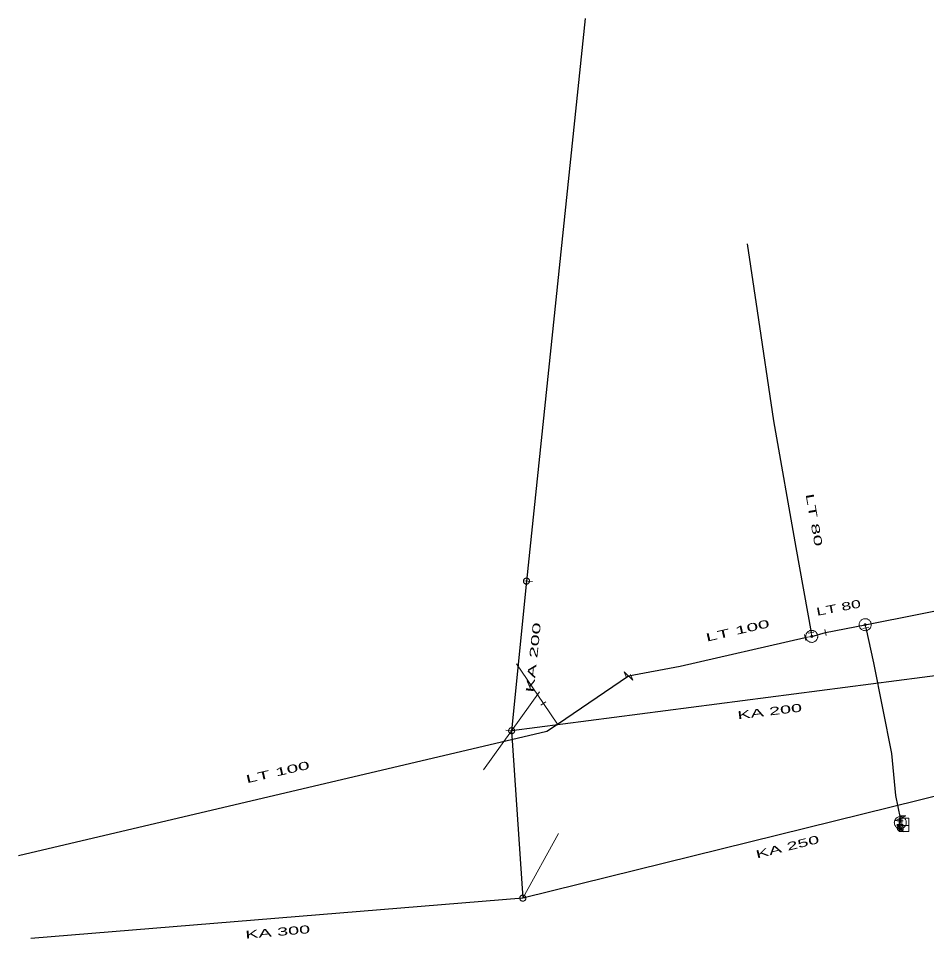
# Model space of a CAD drawing. Extents: x -791009 to -790862, y -978091 to -978015.
# Drawn here: x -791008.6 to -790933, y -978091.4 to -978014.8 of the extents above; entities that cross this region are included whole.
import ezdxf
from ezdxf.enums import TextEntityAlignment as Align

# ---------------------------------------------------------------- set-up
doc = ezdxf.new("R2010")
doc.units = 0
doc.header["$LTSCALE"] = 0.27
doc.layers.add('1', color=7, linetype='Continuous', lineweight=13)

msp = doc.modelspace()

# ---------------------------------------------------------------- linework, layer by layer
at = {"layer": '1', "lineweight": 25}
for p, q in [((-790961.436, -978014.787), (-790966.337, -978061.642)), ((-790966.337, -978061.642), (-790967.57, -978074.1)), ((-790924.866, -978068.572), (-790967.57, -978074.1)), ((-790967.57, -978074.1), (-790966.64, -978088.039)), ((-790923.129, -978077.28), (-790966.64, -978088.039)), ((-790935.21, -978081.39), (-790935.21, -978081.598)), ((-790935.21, -978081.598), (-790935.21, -978081.752)), ((-790966.64, -978088.039), (-791007.609, -978091.399))]:
    msp.add_line(p, q, dxfattribs=at)
at = {"layer": '1'}
for p, q in [((-790966.588, -978061.62), (-790965.846, -978061.684)), ((-790937.837, -978065.464), (-790938.32, -978065.575)), ((-790938.079, -978065.52), (-790938.133, -978065.27)), ((-790943.084, -978066.581), (-790943.195, -978066.098)), ((-790943.14, -978066.34), (-790942.581, -978066.243)), ((-790942.883, -978065.977), (-790942.396, -978065.882)), ((-790942.64, -978065.93), (-790942.581, -978066.243)), ((-790941.481, -978065.677), (-790941.378, -978066.162)), ((-790967.171, -978068.517), (-790964.93, -978071.829)), ((-790958.207, -978069.185), (-790958.004, -978069.654)), ((-790967.57, -978074.1), (-790965.239, -978070.85)), ((-790964.726, -978071.686), (-790965.133, -978071.971)), ((-790963.765, -978073.55), (-790964.93, -978071.829)), ((-790967.57, -978074.1), (-790969.901, -978077.35)), ((-790967.318, -978074.121), (-790968.06, -978074.057)), ((-790934.744, -978081.182), (-790935.255, -978081.194)), ((-790935.5, -978081.923), (-790934.919, -978082.505)), ((-790935.458, -978081.597), (-790934.962, -978081.598)), ((-790934.962, -978081.899), (-790935.458, -978081.898)), ((-790935.21, -978081.752), (-790935.21, -978081.899)), ((-790935.21, -978081.899), (-790935.21, -978082.214)), ((-790935.21, -978082.214), (-790935.21, -978082.489)), ((-790966.64, -978088.039), (-790963.67, -978082.66)), ((-790966.388, -978088.021), (-790967.13, -978088.073))]:
    msp.add_line(p, q, dxfattribs=at)
at = {"layer": '1', "lineweight": 25}
for points in [[(-790947.971, -978033.563), (-790947.133, -978039.149), (-790945.76, -978048.3), (-790943.91, -978058.85), (-790942.64, -978065.93)], [(-790938.133, -978065.27), (-790929.05, -978063.48), (-790923.92, -978062), (-790911.73, -978059.93), (-790910.719, -978060.899), (-790908.14, -978061.89), (-790895.21, -978059.059), (-790884.6, -978056.66), (-790868.534, -978052.874), (-790866.21, -978052.43), (-790863.219, -978051.91)], [(-790942.581, -978066.243), (-790941.43, -978065.92), (-790938.133, -978065.27)], [(-790938.079, -978065.52), (-790937.44, -978068.449), (-790935.949, -978075.989), (-790935.62, -978079.48), (-790935.21, -978081.39)], [(-790957.84, -978069.539), (-790953.55, -978068.73), (-790943.14, -978066.34)], [(-791008.64, -978084.48), (-790964.631, -978074.136), (-790963.765, -978073.55), (-790957.84, -978069.539)]]:
    msp.add_lwpolyline(points, dxfattribs=at)
at = {"layer": '1'}
for points in [[(-790966.315, -978061.39), (-790966.341, -978061.39), (-790966.367, -978061.392), (-790966.393, -978061.396), (-790966.418, -978061.403), (-790966.443, -978061.413), (-790966.466, -978061.425), (-790966.489, -978061.44), (-790966.508, -978061.457), (-790966.527, -978061.476), (-790966.543, -978061.497), (-790966.557, -978061.52), (-790966.569, -978061.543), (-790966.577, -978061.568), (-790966.583, -978061.594), (-790966.588, -978061.62), (-790966.588, -978061.646), (-790966.586, -978061.672), (-790966.582, -978061.698), (-790966.575, -978061.724), (-790966.565, -978061.748), (-790966.553, -978061.771), (-790966.538, -978061.794), (-790966.521, -978061.813), (-790966.502, -978061.832), (-790966.481, -978061.848), (-790966.458, -978061.862), (-790966.435, -978061.874), (-790966.41, -978061.883), (-790966.384, -978061.889), (-790966.358, -978061.893), (-790966.332, -978061.894), (-790966.306, -978061.892), (-790966.28, -978061.887), (-790966.254, -978061.88), (-790966.23, -978061.87), (-790966.207, -978061.858), (-790966.184, -978061.843), (-790966.165, -978061.826), (-790966.146, -978061.807), (-790966.13, -978061.786), (-790966.116, -978061.764), (-790966.104, -978061.74), (-790966.095, -978061.715), (-790966.089, -978061.689), (-790966.085, -978061.663), (-790966.084, -978061.637), (-790966.086, -978061.611), (-790966.091, -978061.585), (-790966.098, -978061.56), (-790966.108, -978061.535), (-790966.12, -978061.512), (-790966.135, -978061.489), (-790966.152, -978061.47), (-790966.171, -978061.451), (-790966.192, -978061.435), (-790966.214, -978061.421), (-790966.238, -978061.409), (-790966.263, -978061.401), (-790966.289, -978061.395)], [(-790937.633, -978065.27), (-790937.636, -978065.218), (-790937.644, -978065.166), (-790937.658, -978065.116), (-790937.676, -978065.067), (-790937.7, -978065.02), (-790937.729, -978064.976), (-790937.762, -978064.936), (-790937.799, -978064.899), (-790937.839, -978064.866), (-790937.883, -978064.837), (-790937.93, -978064.813), (-790937.979, -978064.795), (-790938.029, -978064.781), (-790938.081, -978064.773), (-790938.133, -978064.77), (-790938.185, -978064.773), (-790938.237, -978064.781), (-790938.288, -978064.795), (-790938.336, -978064.813), (-790938.383, -978064.837), (-790938.427, -978064.866), (-790938.468, -978064.899), (-790938.505, -978064.936), (-790938.538, -978064.976), (-790938.566, -978065.02), (-790938.59, -978065.067), (-790938.609, -978065.116), (-790938.622, -978065.166), (-790938.63, -978065.218), (-790938.633, -978065.27), (-790938.63, -978065.322), (-790938.622, -978065.374), (-790938.609, -978065.425), (-790938.59, -978065.473), (-790938.566, -978065.52), (-790938.538, -978065.564), (-790938.505, -978065.605), (-790938.468, -978065.642), (-790938.427, -978065.675), (-790938.383, -978065.703), (-790938.336, -978065.727), (-790938.288, -978065.746), (-790938.237, -978065.759), (-790938.185, -978065.767), (-790938.133, -978065.77), (-790938.081, -978065.767), (-790938.029, -978065.759), (-790937.979, -978065.746), (-790937.93, -978065.727), (-790937.883, -978065.703), (-790937.839, -978065.675), (-790937.799, -978065.642), (-790937.762, -978065.605), (-790937.729, -978065.564), (-790937.7, -978065.52), (-790937.676, -978065.473), (-790937.658, -978065.425), (-790937.644, -978065.374), (-790937.636, -978065.322)], [(-790938.051, -978065.27), (-790938.051, -978065.261), (-790938.053, -978065.253), (-790938.055, -978065.245), (-790938.058, -978065.237), (-790938.062, -978065.229), (-790938.067, -978065.222), (-790938.072, -978065.215), (-790938.078, -978065.209), (-790938.085, -978065.204), (-790938.092, -978065.199), (-790938.1, -978065.195), (-790938.108, -978065.192), (-790938.116, -978065.19), (-790938.124, -978065.188), (-790938.133, -978065.188), (-790938.142, -978065.188), (-790938.15, -978065.19), (-790938.158, -978065.192), (-790938.166, -978065.195), (-790938.174, -978065.199), (-790938.181, -978065.204), (-790938.188, -978065.209), (-790938.194, -978065.215), (-790938.2, -978065.222), (-790938.204, -978065.229), (-790938.208, -978065.237), (-790938.211, -978065.245), (-790938.213, -978065.253), (-790938.215, -978065.261), (-790938.215, -978065.27), (-790938.215, -978065.279), (-790938.213, -978065.287), (-790938.211, -978065.295), (-790938.208, -978065.303), (-790938.204, -978065.311), (-790938.2, -978065.318), (-790938.194, -978065.325), (-790938.188, -978065.331), (-790938.181, -978065.337), (-790938.174, -978065.341), (-790938.166, -978065.345), (-790938.158, -978065.348), (-790938.15, -978065.35), (-790938.142, -978065.352), (-790938.133, -978065.352), (-790938.124, -978065.352), (-790938.116, -978065.35), (-790938.108, -978065.348), (-790938.1, -978065.345), (-790938.092, -978065.341), (-790938.085, -978065.337), (-790938.078, -978065.331), (-790938.072, -978065.325), (-790938.067, -978065.318), (-790938.062, -978065.311), (-790938.058, -978065.303), (-790938.055, -978065.295), (-790938.053, -978065.287), (-790938.051, -978065.279)], [(-790942.58, -978065.743), (-790942.632, -978065.745), (-790942.684, -978065.753), (-790942.734, -978065.767), (-790942.783, -978065.785), (-790942.83, -978065.809), (-790942.874, -978065.838), (-790942.914, -978065.871), (-790942.951, -978065.908), (-790942.984, -978065.948), (-790943.013, -978065.992), (-790943.037, -978066.039), (-790943.055, -978066.088), (-790943.069, -978066.138), (-790943.077, -978066.19), (-790943.081, -978066.242), (-790943.078, -978066.294), (-790943.07, -978066.346), (-790943.056, -978066.397), (-790943.038, -978066.445), (-790943.014, -978066.492), (-790942.985, -978066.536), (-790942.952, -978066.577), (-790942.915, -978066.614), (-790942.875, -978066.647), (-790942.831, -978066.675), (-790942.784, -978066.699), (-790942.735, -978066.718), (-790942.685, -978066.731), (-790942.633, -978066.739), (-790942.581, -978066.743), (-790942.529, -978066.74), (-790942.477, -978066.732), (-790942.426, -978066.719), (-790942.378, -978066.7), (-790942.331, -978066.676), (-790942.287, -978066.648), (-790942.246, -978066.615), (-790942.209, -978066.578), (-790942.176, -978066.537), (-790942.148, -978066.493), (-790942.124, -978066.446), (-790942.105, -978066.398), (-790942.092, -978066.347), (-790942.084, -978066.295), (-790942.081, -978066.243), (-790942.083, -978066.191), (-790942.091, -978066.139), (-790942.104, -978066.089), (-790942.123, -978066.04), (-790942.147, -978065.993), (-790942.175, -978065.949), (-790942.208, -978065.909), (-790942.245, -978065.872), (-790942.286, -978065.839), (-790942.33, -978065.81), (-790942.377, -978065.786), (-790942.425, -978065.768), (-790942.476, -978065.754), (-790942.528, -978065.746)], [(-790942.58, -978066.161), (-790942.589, -978066.161), (-790942.597, -978066.162), (-790942.605, -978066.164), (-790942.613, -978066.167), (-790942.621, -978066.171), (-790942.628, -978066.176), (-790942.635, -978066.181), (-790942.641, -978066.187), (-790942.646, -978066.194), (-790942.651, -978066.201), (-790942.655, -978066.209), (-790942.658, -978066.217), (-790942.66, -978066.225), (-790942.663, -978066.233), (-790942.663, -978066.242), (-790942.663, -978066.251), (-790942.661, -978066.259), (-790942.659, -978066.267), (-790942.656, -978066.275), (-790942.652, -978066.283), (-790942.647, -978066.29), (-790942.642, -978066.297), (-790942.636, -978066.303), (-790942.629, -978066.309), (-790942.622, -978066.313), (-790942.614, -978066.317), (-790942.606, -978066.32), (-790942.598, -978066.322), (-790942.59, -978066.325), (-790942.581, -978066.325), (-790942.572, -978066.325), (-790942.564, -978066.323), (-790942.556, -978066.321), (-790942.548, -978066.318), (-790942.54, -978066.314), (-790942.533, -978066.31), (-790942.526, -978066.304), (-790942.52, -978066.298), (-790942.514, -978066.291), (-790942.51, -978066.284), (-790942.506, -978066.276), (-790942.503, -978066.268), (-790942.501, -978066.26), (-790942.499, -978066.252), (-790942.499, -978066.243), (-790942.499, -978066.234), (-790942.5, -978066.226), (-790942.502, -978066.218), (-790942.505, -978066.21), (-790942.509, -978066.202), (-790942.513, -978066.195), (-790942.519, -978066.188), (-790942.525, -978066.182), (-790942.532, -978066.177), (-790942.539, -978066.172), (-790942.547, -978066.168), (-790942.555, -978066.165), (-790942.563, -978066.163), (-790942.571, -978066.161)], [(-790967.591, -978074.351), (-790967.565, -978074.351), (-790967.539, -978074.349), (-790967.513, -978074.345), (-790967.488, -978074.338), (-790967.463, -978074.328), (-790967.44, -978074.316), (-790967.417, -978074.301), (-790967.398, -978074.284), (-790967.379, -978074.265), (-790967.363, -978074.244), (-790967.349, -978074.221), (-790967.337, -978074.198), (-790967.329, -978074.173), (-790967.323, -978074.147), (-790967.318, -978074.121), (-790967.318, -978074.095), (-790967.32, -978074.069), (-790967.324, -978074.043), (-790967.331, -978074.017), (-790967.341, -978073.993), (-790967.353, -978073.97), (-790967.368, -978073.947), (-790967.385, -978073.928), (-790967.404, -978073.909), (-790967.425, -978073.893), (-790967.448, -978073.879), (-790967.471, -978073.867), (-790967.496, -978073.858), (-790967.522, -978073.852), (-790967.548, -978073.848), (-790967.574, -978073.847), (-790967.6, -978073.849), (-790967.626, -978073.854), (-790967.652, -978073.861), (-790967.676, -978073.871), (-790967.699, -978073.883), (-790967.722, -978073.898), (-790967.741, -978073.915), (-790967.76, -978073.934), (-790967.776, -978073.955), (-790967.79, -978073.977), (-790967.802, -978074.001), (-790967.811, -978074.026), (-790967.817, -978074.052), (-790967.821, -978074.078), (-790967.822, -978074.104), (-790967.82, -978074.13), (-790967.815, -978074.156), (-790967.808, -978074.181), (-790967.798, -978074.206), (-790967.786, -978074.229), (-790967.771, -978074.252), (-790967.754, -978074.271), (-790967.735, -978074.29), (-790967.714, -978074.306), (-790967.692, -978074.32), (-790967.668, -978074.332), (-790967.643, -978074.34), (-790967.617, -978074.346)], [(-790934.71, -978081.752), (-790934.713, -978081.7), (-790934.721, -978081.647), (-790934.735, -978081.598), (-790934.752, -978081.549), (-790934.777, -978081.502), (-790934.806, -978081.458), (-790934.838, -978081.418), (-790934.875, -978081.38), (-790934.916, -978081.348), (-790934.96, -978081.319), (-790935.007, -978081.294), (-790935.056, -978081.277), (-790935.105, -978081.263), (-790935.157, -978081.255), (-790935.21, -978081.252), (-790935.262, -978081.255), (-790935.314, -978081.263), (-790935.365, -978081.277), (-790935.413, -978081.294), (-790935.46, -978081.319), (-790935.504, -978081.348), (-790935.544, -978081.38), (-790935.581, -978081.418), (-790935.615, -978081.458), (-790935.642, -978081.502), (-790935.667, -978081.549), (-790935.686, -978081.598), (-790935.698, -978081.647), (-790935.706, -978081.7), (-790935.71, -978081.752), (-790935.706, -978081.804), (-790935.698, -978081.856), (-790935.686, -978081.907), (-790935.667, -978081.955), (-790935.642, -978082.002), (-790935.615, -978082.046), (-790935.581, -978082.087), (-790935.544, -978082.124), (-790935.504, -978082.157), (-790935.46, -978082.184), (-790935.413, -978082.209), (-790935.365, -978082.228), (-790935.314, -978082.24), (-790935.262, -978082.249), (-790935.21, -978082.252), (-790935.157, -978082.249), (-790935.105, -978082.24), (-790935.056, -978082.228), (-790935.007, -978082.209), (-790934.96, -978082.184), (-790934.916, -978082.157), (-790934.875, -978082.124), (-790934.838, -978082.087), (-790934.806, -978082.046), (-790934.777, -978082.002), (-790934.752, -978081.955), (-790934.735, -978081.907), (-790934.721, -978081.856), (-790934.713, -978081.804)], [(-790935.309, -978081.39), (-790935.309, -978082.489), (-790934.489, -978082.489), (-790934.489, -978081.39)], [(-790935.09, -978081.39), (-790935.09, -978081.989), (-790934.489, -978081.989), (-790934.489, -978081.39)], [(-790935.5, -978081.923), (-790935.434, -978082.033), (-790935.391, -978081.99)], [(-790935.21, -978081.964), (-790935.235, -978081.965), (-790935.262, -978081.969), (-790935.287, -978081.976), (-790935.311, -978081.986), (-790935.335, -978081.998), (-790935.357, -978082.012), (-790935.377, -978082.028), (-790935.396, -978082.047), (-790935.412, -978082.067), (-790935.426, -978082.089), (-790935.438, -978082.112), (-790935.448, -978082.137), (-790935.455, -978082.162), (-790935.458, -978082.188), (-790935.46, -978082.214), (-790935.458, -978082.24), (-790935.455, -978082.266), (-790935.448, -978082.291), (-790935.438, -978082.316), (-790935.426, -978082.339), (-790935.412, -978082.361), (-790935.396, -978082.381), (-790935.377, -978082.4), (-790935.357, -978082.416), (-790935.335, -978082.431), (-790935.311, -978082.442), (-790935.287, -978082.452), (-790935.262, -978082.459), (-790935.235, -978082.463), (-790935.21, -978082.464), (-790935.184, -978082.463), (-790935.157, -978082.459), (-790935.132, -978082.452), (-790935.108, -978082.442), (-790935.085, -978082.431), (-790935.063, -978082.416), (-790935.043, -978082.4), (-790935.024, -978082.381), (-790935.007, -978082.361), (-790934.993, -978082.339), (-790934.982, -978082.316), (-790934.972, -978082.291), (-790934.965, -978082.266), (-790934.961, -978082.24), (-790934.96, -978082.214), (-790934.961, -978082.188), (-790934.965, -978082.162), (-790934.972, -978082.137), (-790934.982, -978082.112), (-790934.993, -978082.089), (-790935.007, -978082.067), (-790935.024, -978082.047), (-790935.043, -978082.028), (-790935.063, -978082.012), (-790935.085, -978081.998), (-790935.108, -978081.986), (-790935.132, -978081.976), (-790935.157, -978081.969), (-790935.184, -978081.965)], [(-790935.348, -978082.242), (-790935.331, -978082.265), (-790935.308, -978082.297), (-790935.284, -978082.305), (-790935.245, -978082.32), (-790935.174, -978082.32), (-790935.135, -978082.305), (-790935.112, -978082.297), (-790935.088, -978082.265), (-790935.071, -978082.242), (-790935.071, -978082.186), (-790935.088, -978082.163), (-790935.112, -978082.135), (-790935.135, -978082.123), (-790935.174, -978082.108), (-790935.245, -978082.108), (-790935.284, -978082.123), (-790935.308, -978082.135), (-790935.331, -978082.163), (-790935.348, -978082.186)], [(-790966.622, -978088.29), (-790966.596, -978088.286), (-790966.57, -978088.28), (-790966.545, -978088.272), (-790966.522, -978088.261), (-790966.499, -978088.247), (-790966.478, -978088.232), (-790966.458, -978088.213), (-790966.441, -978088.194), (-790966.426, -978088.172), (-790966.413, -978088.149), (-790966.403, -978088.124), (-790966.395, -978088.1), (-790966.39, -978088.073), (-790966.388, -978088.047), (-790966.388, -978088.021), (-790966.392, -978087.995), (-790966.398, -978087.969), (-790966.406, -978087.944), (-790966.417, -978087.92), (-790966.431, -978087.898), (-790966.446, -978087.877), (-790966.465, -978087.857), (-790966.484, -978087.84), (-790966.506, -978087.825), (-790966.529, -978087.812), (-790966.554, -978087.802), (-790966.578, -978087.794), (-790966.605, -978087.788), (-790966.631, -978087.786), (-790966.657, -978087.787), (-790966.683, -978087.79), (-790966.709, -978087.796), (-790966.734, -978087.805), (-790966.758, -978087.816), (-790966.78, -978087.83), (-790966.801, -978087.845), (-790966.821, -978087.864), (-790966.838, -978087.883), (-790966.853, -978087.905), (-790966.866, -978087.928), (-790966.876, -978087.952), (-790966.884, -978087.977), (-790966.89, -978088.004), (-790966.892, -978088.03), (-790966.891, -978088.056), (-790966.888, -978088.082), (-790966.882, -978088.108), (-790966.873, -978088.133), (-790966.862, -978088.156), (-790966.848, -978088.179), (-790966.833, -978088.2), (-790966.814, -978088.22), (-790966.795, -978088.237), (-790966.773, -978088.252), (-790966.75, -978088.265), (-790966.726, -978088.275), (-790966.701, -978088.283), (-790966.674, -978088.288), (-790966.648, -978088.29)]]:
    msp.add_lwpolyline(points, close=True, dxfattribs=at)
for points in [[(-790958.207, -978069.185), (-790957.472, -978069.892), (-790957.675, -978069.423)], [(-790934.744, -978081.182), (-790935.675, -978081.597), (-790935.164, -978081.585)]]:
    msp.add_lwpolyline(points, dxfattribs=at)

# ---------------------------------------------------------------- texts
for s, rotation, width, p in [('LT 80 ', 280, 1.95, (-790942.671, -978056.84)), ('LT 80 ', 11, 1.65, (-790940.088, -978064.138)), ('KA 200', 84, 2, (-790965.439, -978068.037)), ('LT 100', 13, 1.95, (-790948.682, -978066.077)), ('KA 200', 7, 1.85, (-790946.045, -978072.823)), ('LT 100', 13, 1.95, (-790986.977, -978077.865)), ('KA 250', 14, 1.85, (-790944.528, -978084.088)), ('KA 300', 5, 1.85, (-790987.022, -978091.184))]:
    msp.add_text(s, height=0.6667, rotation=rotation, dxfattribs=dict(at, width=width)).set_placement(p, align=Align.CENTER)

doc.saveas('drawing.dxf')
